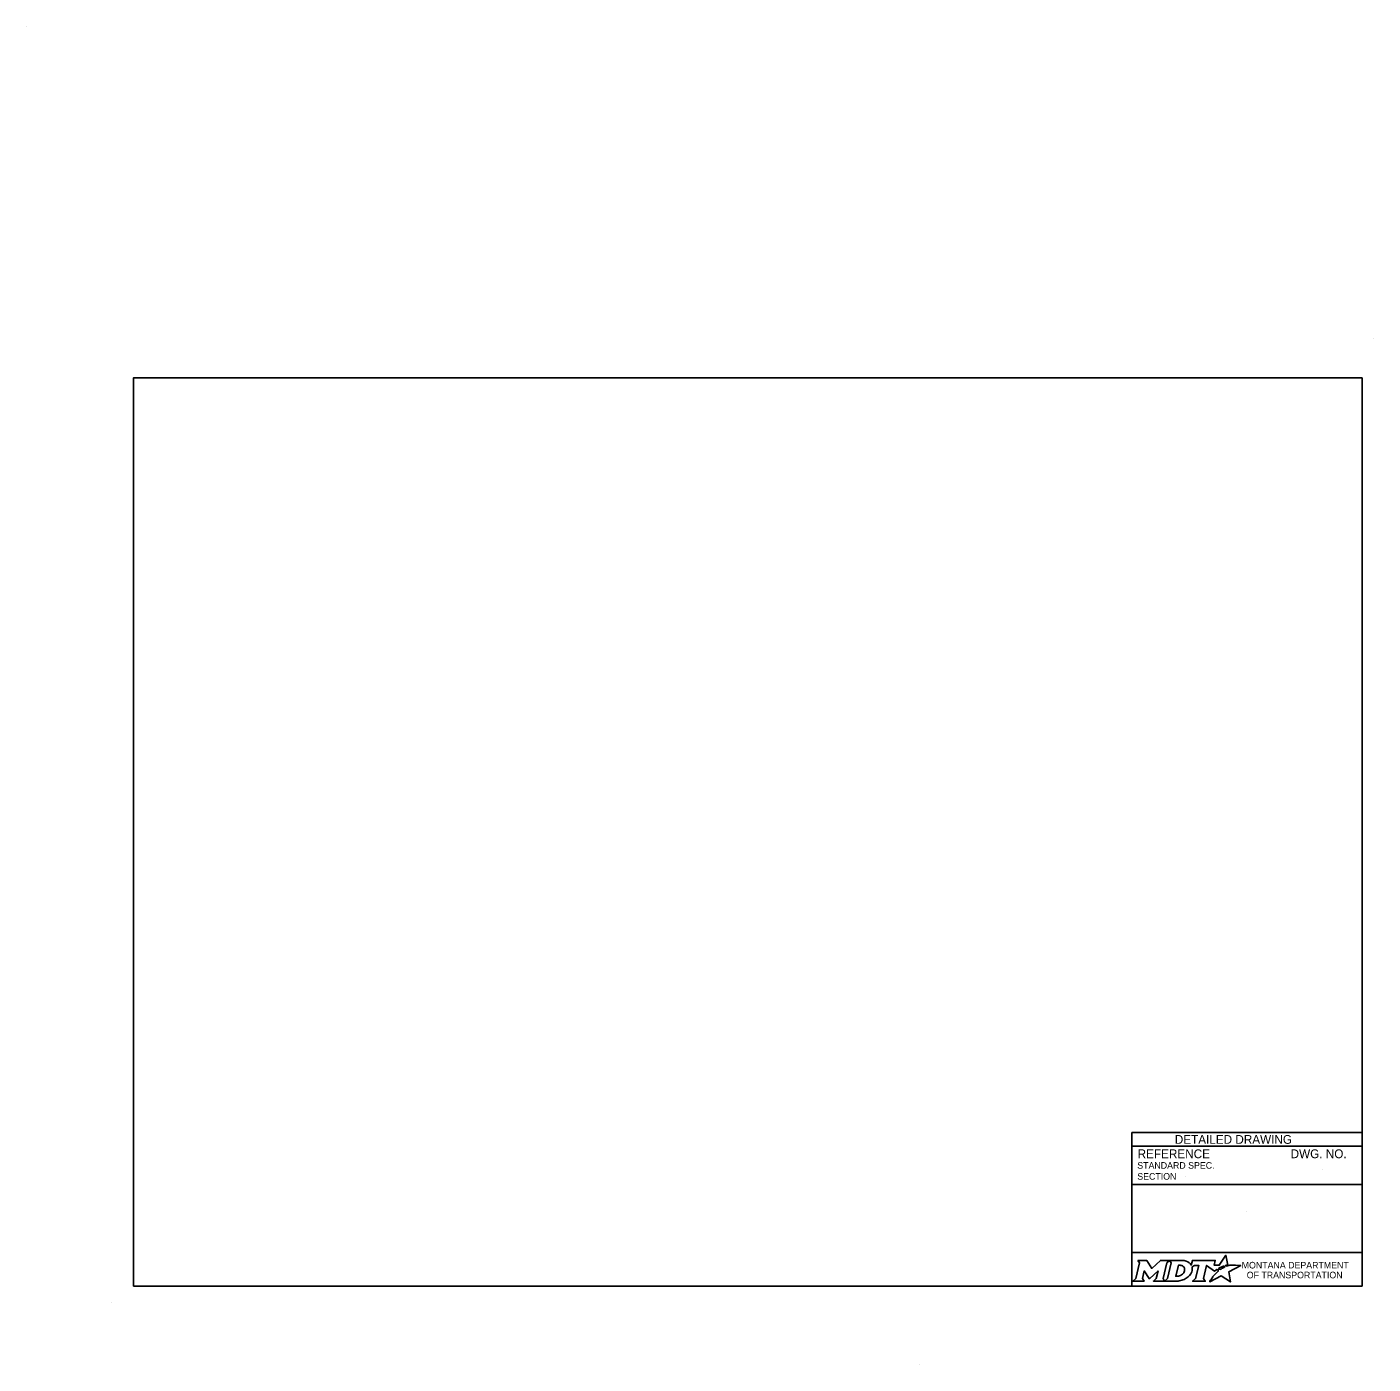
# Model space of a CAD drawing. Extents: x 49991 to 50288, y 49919 to 50011.
# Drawn here: x 50008.76 to 50021.04, y 49999.18 to 50011.36 of the extents above; entities that cross this region are included whole.
import ezdxf

# ---------------------------------------------------------------- set-up
doc = ezdxf.new("R2010")
doc.units = 0
for name, color, linetype in [('Default', 7, 'Continuous'), ('Level 1', 7, 'Continuous'), ('Level 4', 7, 'Continuous')]:
    doc.layers.add(name, color=color, linetype=linetype)

msp = doc.modelspace()

# ---------------------------------------------------------------- linework, layer by layer
at = {"layer": 'Default'}
for points in [[(50018.893, 50000.121), (50018.907, 50000.097), (50018.874, 49999.954), (50018.848, 49999.931), (50018.95, 49999.931), (50018.936, 49999.954), (50018.952, 50000.024), (50018.996, 49999.955), (50019.002, 49999.955), (50019.077, 50000.025), (50019.06, 49999.954), (50019.035, 49999.932), (50019.137, 49999.932), (50019.123, 49999.955), (50019.156, 50000.097)], [(50018.893, 50000.121), (50018.907, 50000.097), (50018.874, 49999.954), (50018.848, 49999.931), (50018.95, 49999.931), (50018.936, 49999.954), (50018.952, 50000.024), (50018.996, 49999.955), (50019.002, 49999.955), (50019.077, 50000.025), (50019.06, 49999.954), (50019.035, 49999.932), (50019.137, 49999.932), (50019.123, 49999.955), (50019.156, 50000.097)], [(50019.156, 50000.097), (50019.182, 50000.121), (50019.099, 50000.121), (50019.02, 50000.048), (50018.975, 50000.12), (50018.893, 50000.121)], [(50019.156, 50000.097), (50019.182, 50000.121), (50019.099, 50000.121), (50019.02, 50000.048), (50018.975, 50000.12), (50018.893, 50000.121)], [(50019.295, 50000.121), (50019.182, 50000.121), (50019.196, 50000.098), (50019.163, 49999.954), (50019.137, 49999.932), (50019.248, 49999.932)], [(50019.295, 50000.121), (50019.182, 50000.121), (50019.196, 50000.098), (50019.163, 49999.954), (50019.137, 49999.932), (50019.248, 49999.932)], [(50019.7, 50000.068), (50019.69, 50000.074), (50019.702, 50000.076), (50019.713, 50000.078), (50019.696, 50000.168), (50019.636, 50000.077), (50019.589, 50000.076), (50019.599, 50000.12), (50019.39, 50000.121), (50019.38, 50000.078), (50019.374, 50000.086)], [(50019.7, 50000.068), (50019.69, 50000.074), (50019.702, 50000.076), (50019.713, 50000.078), (50019.696, 50000.168), (50019.636, 50000.077), (50019.589, 50000.076), (50019.599, 50000.12), (50019.39, 50000.121), (50019.38, 50000.078), (50019.374, 50000.086)], [(50019.319, 50000.034), (50019.318, 50000.026), (50019.315, 50000.017), (50019.311, 50000.008), (50019.305, 50000.001), (50019.299, 49999.994), (50019.291, 49999.988), (50019.282, 49999.983), (50019.273, 49999.979), (50019.264, 49999.977), (50019.255, 49999.976), (50019.239, 49999.976), (50019.263, 50000.076), (50019.279, 50000.076), (50019.286, 50000.075), (50019.294, 50000.073), (50019.301, 50000.07), (50019.307, 50000.066), (50019.311, 50000.061), (50019.315, 50000.055), (50019.318, 50000.049), (50019.319, 50000.042), (50019.32, 50000.038), (50019.319, 50000.034)], [(50019.319, 50000.034), (50019.318, 50000.026), (50019.315, 50000.017), (50019.311, 50000.008), (50019.305, 50000.001), (50019.299, 49999.994), (50019.291, 49999.988), (50019.282, 49999.983), (50019.273, 49999.979), (50019.264, 49999.977), (50019.255, 49999.976), (50019.239, 49999.976), (50019.263, 50000.076), (50019.279, 50000.076), (50019.286, 50000.075), (50019.294, 50000.073), (50019.301, 50000.07), (50019.307, 50000.066), (50019.311, 50000.061), (50019.315, 50000.055), (50019.318, 50000.049), (50019.319, 50000.042), (50019.32, 50000.038), (50019.319, 50000.034)], [(50019.387, 50000.062), (50019.411, 50000.075), (50019.448, 50000.075), (50019.42, 49999.954), (50019.392, 49999.931), (50019.508, 49999.931), (50019.491, 49999.954), (50019.52, 50000.075), (50019.591, 50000.023), (50019.612, 50000.038), (50019.632, 50000.027)], [(50019.387, 50000.062), (50019.411, 50000.075), (50019.448, 50000.075), (50019.42, 49999.954), (50019.392, 49999.931), (50019.508, 49999.931), (50019.491, 49999.954), (50019.52, 50000.075), (50019.591, 50000.023), (50019.612, 50000.038), (50019.632, 50000.027)], [(50019.576, 49999.971), (50019.561, 49999.947), (50019.556, 49999.939), (50019.55, 49999.931), (50019.548, 49999.926), (50019.653, 49999.979), (50019.737, 49999.924), (50019.724, 50000.017), (50019.831, 50000.075), (50019.782, 50000.076), (50019.751, 50000.077), (50019.731, 50000.077), (50019.724, 50000.075), (50019.719, 50000.074), (50019.711, 50000.072), (50019.7, 50000.068)], [(50019.576, 49999.971), (50019.561, 49999.947), (50019.556, 49999.939), (50019.55, 49999.931), (50019.548, 49999.926), (50019.653, 49999.979), (50019.737, 49999.924), (50019.724, 50000.017), (50019.831, 50000.075), (50019.782, 50000.076), (50019.751, 50000.077), (50019.731, 50000.077), (50019.724, 50000.075), (50019.719, 50000.074), (50019.711, 50000.072), (50019.7, 50000.068)], [(50019.59, 49999.987), (50019.59, 49999.987)], [(50019.59, 49999.987), (50019.59, 49999.987)], [(50019.65, 50000.04), (50019.648, 50000.039), (50019.629, 50000.048), (50019.639, 50000.054), (50019.644, 50000.056), (50019.652, 50000.06), (50019.658, 50000.063), (50019.666, 50000.066), (50019.673, 50000.068), (50019.685, 50000.061), (50019.681, 50000.059), (50019.676, 50000.056), (50019.672, 50000.054), (50019.667, 50000.051), (50019.665, 50000.05), (50019.662, 50000.049), (50019.66, 50000.047), (50019.658, 50000.046), (50019.655, 50000.044), (50019.652, 50000.042), (50019.65, 50000.04)], [(50019.65, 50000.04), (50019.648, 50000.039), (50019.629, 50000.048), (50019.639, 50000.054), (50019.644, 50000.056), (50019.652, 50000.06), (50019.658, 50000.063), (50019.666, 50000.066), (50019.673, 50000.068), (50019.685, 50000.061), (50019.681, 50000.059), (50019.676, 50000.056), (50019.672, 50000.054), (50019.667, 50000.051), (50019.665, 50000.05), (50019.662, 50000.049), (50019.66, 50000.047), (50019.658, 50000.046), (50019.655, 50000.044), (50019.652, 50000.042), (50019.65, 50000.04)], [(50019.293, 49999.939), (50019.302, 49999.942), (50019.315, 49999.947), (50019.335, 49999.958)], [(50019.293, 49999.939), (50019.302, 49999.942), (50019.315, 49999.947), (50019.335, 49999.958)]]:
    msp.add_lwpolyline(points, dxfattribs=at)
for centre, radius, start, end in [((50019.274, 50000.059), 0.118, 300.9103, 339.1383), ((50019.274, 50000.059), 0.118, 300.9103, 339.1383), ((50019.319, 50000.042), 0.0709, 339.5329, 15.8582), ((50019.319, 50000.042), 0.0709, 339.5329, 15.8582)]:
    msp.add_arc(centre, radius, start, end, dxfattribs=at)
for centre, major_axis, ratio, start_param, end_param in [((50019.293, 50000.073), (0.0834, -0.0037), 0.568097, 0.61298, 1.570796), ((50019.293, 50000.073), (0.0834, -0.0037), 0.568097, 0.61298, 1.570796), ((50019.349, 50000.081), (0.0361, -0.0295), 0.469099, 1.225588, 1.570796), ((50019.349, 50000.081), (0.0361, -0.0295), 0.469099, 1.225588, 1.570796), ((50019.583, 49999.979), (-0.00694, -0.00806), 0.008222, 0, 3.137361), ((50019.583, 49999.979), (-0.00694, -0.00806), 0.008222, 0, 3.137361), ((50019.6, 49999.997), (-0.0098, -0.0102), 0.016458, 3.141593, 6.279097), ((50019.6, 49999.997), (-0.0098, -0.0102), 0.016458, 3.141593, 6.279097), ((50019.621, 50000.017), (-0.0112, -0.0097), 0.021651, 3.157348, 6.283185), ((50019.621, 50000.017), (-0.0112, -0.0097), 0.021651, 3.157348, 6.283185), ((50019.248, 50000.08), (0, 0.148), 0.987302, 3.139398, 3.456847), ((50019.248, 50000.08), (0, 0.148), 0.987302, 3.139398, 3.456847)]:
    msp.add_ellipse(centre, major_axis=major_axis, ratio=ratio, start_param=start_param, end_param=end_param, dxfattribs=at)
at = {"layer": 'Level 1'}
for p, q in [((50008.765, 50011.363), (50008.765, 50011.363)), ((50008.765, 50011.363), (50008.765, 50011.363)), ((50021.038, 50008.524), (50021.038, 50008.524)), ((50021.038, 50008.524), (50021.038, 50008.524)), ((50009.537, 49999.736), (50009.537, 49999.736)), ((50009.537, 49999.736), (50009.537, 49999.736)), ((50016.9, 49999.176), (50016.9, 49999.176)), ((50016.9, 49999.176), (50016.9, 49999.176))]:
    msp.add_line(p, q, dxfattribs=at)
msp.add_lwpolyline([(50020.938, 50008.165), (50009.737, 50008.165), (50009.737, 49999.886), (50020.938, 49999.886)], close=True, dxfattribs=at)
msp.add_lwpolyline([(50020.938, 50008.165), (50009.737, 50008.165), (50009.737, 49999.886), (50020.938, 49999.886)], close=True, dxfattribs=at)
at = {"layer": 'Level 4'}
for p, q in [((50020.938, 50001.286), (50018.838, 50001.286)), ((50018.838, 50001.286), (50018.838, 49999.886)), ((50020.938, 50001.286), (50018.838, 50001.286)), ((50018.838, 50001.286), (50018.838, 49999.886)), ((50020.938, 50001.161), (50018.838, 50001.161)), ((50020.938, 50001.161), (50018.838, 50001.161)), ((50019.332, 50000.886), (50019.332, 50000.886)), ((50019.332, 50000.886), (50019.332, 50000.886)), ((50020.574, 50000.946), (50020.574, 50000.946)), ((50020.574, 50000.946), (50020.574, 50000.946)), ((50020.938, 50000.811), (50018.838, 50000.811)), ((50020.938, 50000.811), (50018.838, 50000.811)), ((50019.888, 50000.562), (50019.888, 50000.562)), ((50019.888, 50000.562), (50019.888, 50000.562)), ((50020.938, 50000.193), (50018.838, 50000.193)), ((50020.938, 50000.193), (50018.838, 50000.193))]:
    msp.add_line(p, q, dxfattribs=at)

# ---------------------------------------------------------------- texts
at = {"layer": 'Default'}
for s, p in [('MONTANA DEPARTMENT', (50019.84, 50000.047)), ('MONTANA DEPARTMENT', (50019.84, 50000.047)), ('OF TRANSPORTATION', (50019.886, 49999.957)), ('OF TRANSPORTATION', (50019.886, 49999.957))]:
    msp.add_text(s, height=0.06, rotation=360, dxfattribs=at).set_placement(p)
at = {"layer": 'Level 4'}
for s, height, p in [('DETAILED DRAWING', 0.0799, (50019.23, 50001.183)), ('DETAILED DRAWING', 0.0799, (50019.23, 50001.183)), ('REFERENCE', 0.08, (50018.891, 50001.052)), ('REFERENCE', 0.08, (50018.891, 50001.052)), ('DWG. NO.', 0.08, (50020.286, 50001.052)), ('DWG. NO.', 0.08, (50020.286, 50001.052)), ('STANDARD SPEC.', 0.06, (50018.888, 50000.956)), ('STANDARD SPEC.', 0.06, (50018.888, 50000.956)), ('SECTION', 0.06, (50018.888, 50000.856)), ('SECTION', 0.06, (50018.888, 50000.856))]:
    msp.add_text(s, height=height, dxfattribs=at).set_placement(p)

doc.saveas('drawing.dxf')
